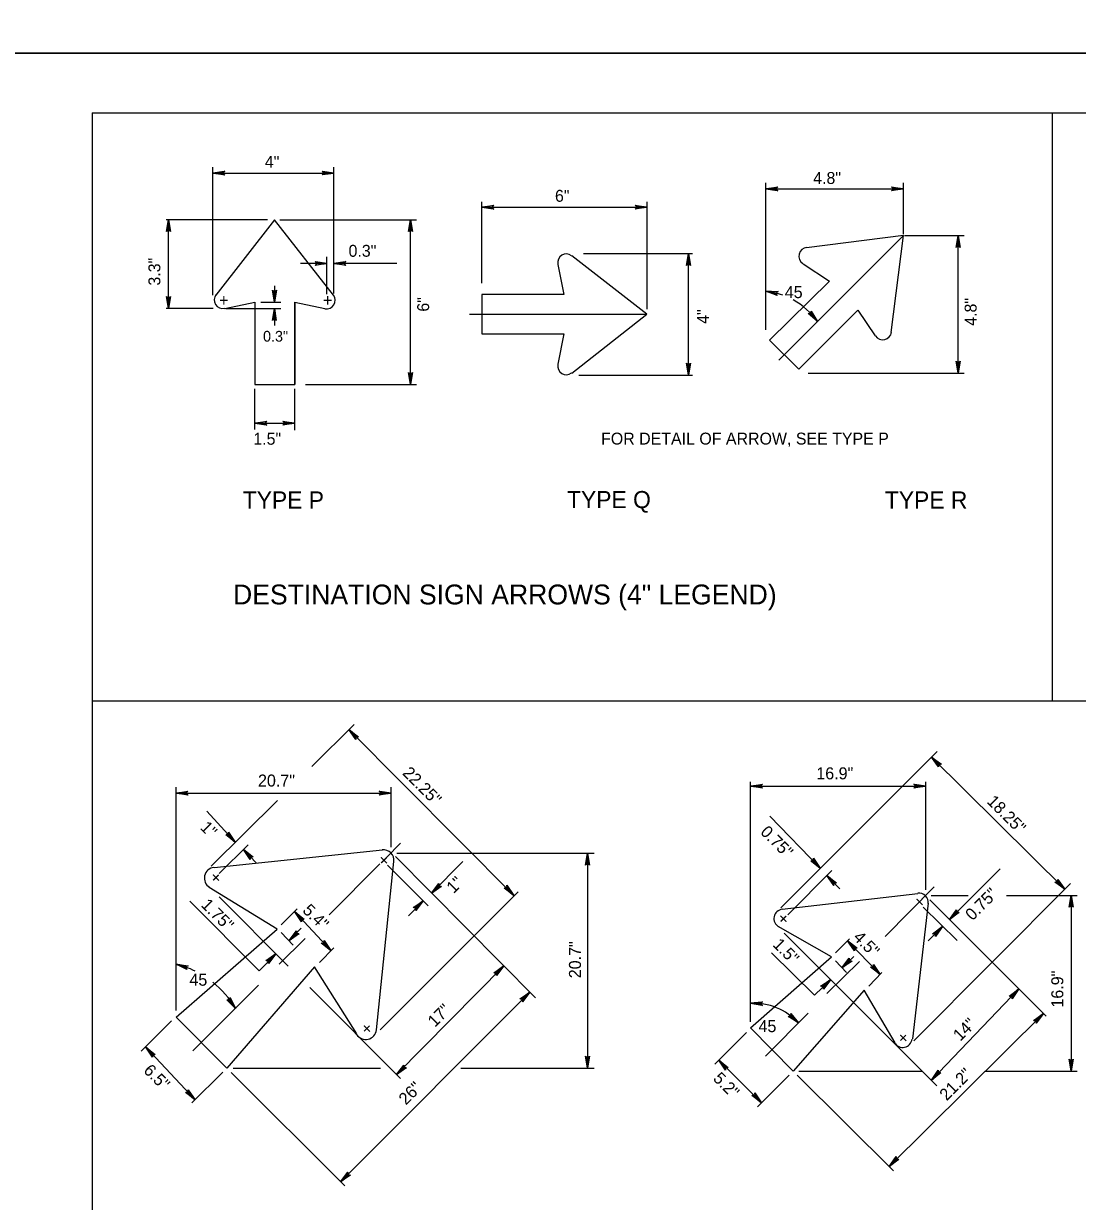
# Model space of a CAD drawing. Extents: x 638421 to 641849, y 297270 to 299646.
# Drawn here: x 640967.1 to 641232.4, y 298762.6 to 299059.1 of the extents above; entities that cross this region are included whole.
import ezdxf

# ---------------------------------------------------------------- set-up
doc = ezdxf.new("R2010")
doc.units = 0
for name, color, linetype in [('1', 7, 'Continuous'), ('2', 7, 'Continuous'), ('3', 7, 'Continuous'), ('XCS-GRID-HVGL', 7, 'Continuous')]:
    doc.layers.add(name, color=color, linetype=linetype)

# ---------------------------------------------------------------- blocks, each defined once
blk = doc.blocks.new('RARROW')
at = {"layer": '3'}
blk.add_lwpolyline([(-2.2695, 0.285), (-2.184875, 0.12075), (0, 0), (-2.2695, 0.285), (-2.38575, 0.384625), (0, 0), (-2.183125, -0.108), (-2.262875, -0.2705), (0, 0), (-2.38575, -0.379125), (-2.262875, -0.2705)], dxfattribs=at)

msp = doc.modelspace()

# ---------------------------------------------------------------- linework, layer by layer
at = {"layer": '1'}
for q in [(641770.31, 299036.63), (640984.31, 298472.63)]:
    msp.add_line((640984.31, 299036.63), q, dxfattribs=at)
for points in [[(641226.06, 298888.5), (641226.06, 299036.63)], [(641770.31, 298888.5), (640984.31, 298888.5)]]:
    msp.add_lwpolyline(points, dxfattribs=at)
at = {"layer": '2'}
for p, q in [((641014.69, 298990.75), (641014.69, 299023)), ((641014.69, 299021.5), (641045.19, 299021.5)), ((641045.19, 298991.13), (641045.19, 299023)), ((641153.94, 298982), (641153.94, 299019)), ((641188.56, 299006.13), (641188.56, 299019)), ((641153.94, 299017.5), (641188.56, 299017.5)), ((641082.44, 298993.75), (641082.44, 299014.25)), ((641082.44, 299012.88), (641124.06, 299012.88)), ((641124.06, 298987.25), (641124.06, 299014.25)), ((641028.44, 299009.75), (641002.94, 299009.75)), ((641003.56, 298987.38), (641003.56, 299009.75)), ((641030.19, 299009.75), (641015.44, 298990.75)), ((641045.06, 298990.75), (641030.19, 299009.75)), ((641031.56, 299009.75), (641065.94, 299009.75)), ((641064.44, 298968.25), (641064.44, 299009.75)), ((641157.19, 298974.38), (641188.56, 299005.75)), ((641188.56, 299005.75), (641164.19, 299002.63)), ((641185.44, 298981.38), (641188.56, 299005.75)), ((641188.81, 299005.75), (641203.81, 299005.75)), ((641202.31, 298971.13), (641202.31, 299005.75)), ((641043.44, 298991), (641043.44, 299000.38)), ((641045.19, 298991.13), (641045.19, 299000.38)), ((641123.94, 298986), (641105.06, 299000.63)), ((641108.06, 299001.25), (641135.44, 299001.25)), ((641134.46, 298970.63), (641134.46, 299001.25)), ((641043.44, 298998.75), (641036.81, 298998.75)), ((641061.01, 298998.75), (641045.19, 298998.75)), ((641101.56, 298998.5), (641103.06, 298990.88)), ((641163.31, 298998.63), (641169.94, 298994.25)), ((641169.94, 298994.25), (641154.81, 298979.38)), ((641030.19, 298993.13), (641030.19, 298989)), ((641017.69, 298987.38), (641025.31, 298989)), ((641025.31, 298989), (641025.31, 298968.25)), ((641025.31, 298989), (641025.31, 298968.25)), ((641026.81, 298989), (641031.81, 298989)), ((641035.31, 298968.25), (641035.31, 298989)), ((641035.31, 298989), (641042.94, 298987.38)), ((641035.31, 298989), (641035.31, 298968.25)), ((641035.31, 298989), (641035.31, 298968.25)), ((641082.44, 298990.88), (641082.44, 298981)), ((641103.06, 298990.88), (641082.44, 298990.88)), ((641014.81, 298987.38), (641002.94, 298987.38)), ((641017.94, 298987.38), (641031.81, 298987.38)), ((641030.19, 298987.38), (641030.19, 298983.13)), ((641079.31, 298986), (641123.94, 298986)), ((641105.06, 298971.13), (641123.94, 298986)), ((641162.19, 298972.13), (641177.06, 298987)), ((641177.06, 298987), (641181.44, 298980.5)), ((641082.44, 298981), (641103.06, 298981)), ((641103.06, 298981), (641101.56, 298973.38)), ((641154.81, 298979.38), (641162.19, 298972.13)), ((641106.81, 298970.63), (641135.44, 298970.63)), ((641164.56, 298971.13), (641203.81, 298971.13)), ((641025.31, 298968.25), (641035.31, 298968.25)), ((641038.06, 298968.25), (641065.94, 298968.25)), ((641025.31, 298956.88), (641025.31, 298967.13)), ((641035.31, 298956.75), (641035.31, 298967.13)), ((641025.31, 298958.5), (641035.31, 298958.5)), ((641039.62, 298872.11), (641050.28, 298882.68)), ((641048.98, 298881.39), (641090.44, 298839.63)), ((641157.69, 298836.5), (641197.03, 298875.84)), ((641195.61, 298874.43), (641229.19, 298841.17)), ((641005.44, 298810.63), (641005.44, 298866.88)), ((641059.56, 298851.75), (641059.56, 298866.88)), ((641150.06, 298807.75), (641150.06, 298868.25)), ((641150.06, 298867.13), (641150.06, 298867.13)), ((641150.06, 298867.13), (641194.19, 298867.13)), ((641194.19, 298841), (641194.19, 298868.25)), ((641005.44, 298865.38), (641059.56, 298865.38)), ((641014.31, 298847), (641030.98, 298863.54)), ((641020.36, 298853), (641013.18, 298860.81)), ((641167.63, 298846.44), (641154.9, 298859.59)), ((641016.31, 298845.13), (641023.56, 298852.38)), ((641061.94, 298852.75), (641058.41, 298849.2)), ((641015.06, 298846.63), (641057.44, 298851.13)), ((641022.4, 298851.21), (641025.69, 298847.75)), ((641059.56, 298850.25), (641059.56, 298850.25)), ((641059.56, 298850.25), (641059.56, 298850.25)), ((641059.56, 298850.25), (641059.56, 298850.25)), ((641060.69, 298849.38), (641095.95, 298813.81)), ((641061.06, 298850.25), (641110.69, 298850.25)), ((641109.06, 298850.25), (641109.06, 298796.13)), ((641056.75, 298847.53), (641043.98, 298834.69)), ((641060.19, 298848.13), (641055.81, 298805.75)), ((641058.69, 298847.25), (641068.94, 298837)), ((641069.77, 298840.21), (641077.68, 298848.12)), ((641159.44, 298834.75), (641170.56, 298845.88)), ((641200.15, 298833.52), (641212.91, 298846.28)), ((641015.31, 298843.88), (641015.31, 298843.88)), ((641169.31, 298844.63), (641172.54, 298841.27)), ((641030.94, 298831.13), (641013.81, 298841.63)), ((641056.81, 298805.75), (641091.56, 298840.5)), ((641158.06, 298836.13), (641192.19, 298840.13)), ((641183.98, 298829.29), (641196.31, 298841.75)), ((641191.19, 298803), (641230.6, 298842.59)), ((641008.9, 298838.18), (641026.36, 298820.67)), ((641016.31, 298839.25), (641033.68, 298821.84)), ((641067.69, 298838.25), (641063.94, 298834.5)), ((641194.81, 298837.63), (641190.81, 298803.5)), ((641194.19, 298839.63), (641194.19, 298839.63)), ((641194.19, 298839.63), (641194.19, 298839.63)), ((641195.19, 298838.5), (641203.69, 298830)), ((641195.19, 298838.5), (641224.46, 298809.23)), ((641195.56, 298839.63), (641204.84, 298839.63)), ((641214.47, 298839.63), (641232.31, 298839.63)), ((641230.81, 298839.63), (641230.81, 298839.63)), ((641230.81, 298839.63), (641230.81, 298795.38)), ((641031.94, 298832.25), (641035.92, 298836.23)), ((641035.31, 298835.5), (641044.43, 298825.71)), ((641193.56, 298836.63), (641202.06, 298828.25)), ((641005.44, 298809), (641030.94, 298831.13)), ((641030.94, 298831.13), (641030.94, 298831.13)), ((641033.94, 298828.25), (641036.94, 298831.38)), ((641170.44, 298824.13), (641157.06, 298831.75)), ((641198.37, 298831.77), (641194.78, 298828.19)), ((641031.43, 298822.33), (641037.94, 298828.75)), ((641031.94, 298830.25), (641034.94, 298827.13)), ((641158.56, 298830.13), (641197, 298791.69)), ((641171.44, 298825.13), (641174.98, 298828.66)), ((641174.52, 298828.21), (641182.69, 298819.69)), ((641030.56, 298824.88), (641026.36, 298820.67)), ((641041.56, 298822.75), (641045.14, 298826.43)), ((641155.37, 298825.18), (641166.18, 298814.53)), ((641150.06, 298806.25), (641170.44, 298824.13)), ((641169.31, 298814.88), (641177.5, 298822.96)), ((641171.44, 298823.13), (641174.19, 298820.25)), ((641173.09, 298821.4), (641176.06, 298824.25)), ((641005.44, 298821.88), (641005.44, 298821.88)), ((641040.31, 298821.63), (641018.19, 298796.13)), ((641040.31, 298821.63), (641040.31, 298821.63)), ((641050.94, 298804.75), (641040.31, 298821.63)), ((641087.97, 298821.85), (641060.94, 298794.5)), ((641174.69, 298820), (641174.69, 298820)), ((641179.81, 298816.75), (641183.16, 298820.17)), ((641009.69, 298800.5), (641026.18, 298817)), ((641015.19, 298817.38), (641015.19, 298817.38)), ((641039.1, 298816.4), (641061.94, 298793.5)), ((641170.25, 298818.44), (641166.18, 298814.53)), ((641171.69, 298817.13), (641171.69, 298817.13)), ((641195.59, 298793.1), (641217.62, 298816.07)), ((641217.56, 298816), (641217.56, 298816)), ((641046.81, 298767.5), (641094.54, 298815.23)), ((641178.69, 298815.75), (641160.81, 298795.38)), ((641186.44, 298802.5), (641178.69, 298815.75)), ((641004.31, 298808), (640996.69, 298800.38)), ((641018.19, 298796.13), (641005.44, 298809)), ((641153.81, 298799.13), (641164.56, 298810)), ((641184.94, 298771.38), (641223.78, 298809.91)), ((641149.06, 298805.13), (641141.06, 298797.13)), ((641160.81, 298795.38), (641150.06, 298806.25)), ((640997.81, 298801.38), (641010.22, 298788.16)), ((641155.56, 298800.88), (641155.56, 298800.88)), ((641188.31, 298800.38), (641188.31, 298800.38)), ((641019.81, 298796.13), (641056.95, 298796.13)), ((641077.16, 298796.13), (641110.69, 298796.13)), ((641142.06, 298798.13), (641152.81, 298787.38)), ((641162.19, 298795.38), (641193.31, 298795.38)), ((641209.08, 298795.38), (641232.31, 298795.38)), ((641017.19, 298795.13), (641009.44, 298787.38)), ((641019.31, 298795), (641047.94, 298766.5)), ((641159.81, 298794.38), (641151.81, 298786.38)), ((641161.81, 298794.38), (641186.06, 298770.25))]:
    msp.add_line(p, q, dxfattribs=at)
for centre, radius, start, end in [((641103.67, 298998.98), 2.16, 51.9885, 191.4212), ((641164.46, 299000.56), 2.21, 96.9885, 236.4212), ((641151.82, 298973.2), 18.65, 70.1319, 83.4312), ((641017.23, 298989.56), 2.16, 141.9885, 281.4212), ((641043.36, 298989.42), 2.16, 258.5788, 38.0115), ((641151.82, 298973.2), 18.65, 35.9325, 61.1367), ((641183.34, 298981.69), 2.21, 213.5788, 353.0115), ((641103.67, 298972.87), 2.16, 168.5788, 308.0115), ((641057.62, 298848.39), 2.7, 354.0498, 95.9502), ((641015.27, 298843.98), 2.7, 95.9502, 238.4461), ((641192.45, 298837.83), 2.36, 353.2204, 96.7795), ((641158.32, 298833.78), 2.36, 96.7795, 240.0676), ((640999.93, 298799.29), 23.64, 64.1532, 76.5153), ((640999.93, 298799.29), 23.64, 30.0986, 51.4068), ((641150.92, 298797.35), 15.12, 42.2634, 93.2507), ((641150.92, 298797.35), 15.12, 42.2634, 43.751), ((641053.21, 298806.04), 2.7, 211.5539, 354.0498), ((641188.39, 298803.71), 2.36, 209.9324, 353.2204)]:
    msp.add_arc(centre, radius, start, end, dxfattribs=at)
at = {"layer": 'XCS-GRID-HVGL'}
for points in [[(640944.31, 299645.63), (641785.31, 299645.63), (641785.31, 299051.63), (640944.31, 299051.63)], [(640944.31, 299051.63), (641785.31, 299051.63), (641785.31, 298457.63), (640944.31, 298457.63)]]:
    msp.add_lwpolyline(points, close=True, dxfattribs=at)

# ---------------------------------------------------------------- block references
at = {"layer": '2'}
for p, xscale, yscale, rotation in [((641014.69, 299021.5), 1.2574347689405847, 1.3092961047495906, 180), ((641153.94, 299017.5), 1.2574347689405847, 1.3092961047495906, 180), ((641082.44, 299012.88), 1.2574347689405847, 1.3092961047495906, 180), ((641003.56, 299009.75), 1.2574347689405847, 1.3092961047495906, 89.99999999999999), ((641064.44, 299009.75), 1.2574347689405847, 1.3092961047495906, 89.99999999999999), ((641202.31, 299005.75), 1.2574347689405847, 1.3092961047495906, 89.99999999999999), ((641134.46, 299001.25), 1.2574347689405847, 1.3092961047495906, 89.99999999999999), ((641045.19, 298998.75), 1.2574347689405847, 1.3092961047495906, 180), ((641030.19, 298989), 1.2574347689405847, 1.3092961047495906, -90.00000000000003), ((641153.95, 298991.73), 1.2574347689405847, 1.3092961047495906, 169.44923148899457), ((641003.56, 298987.38), 1.2574347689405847, 1.3092961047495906, -90.00000000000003), ((641030.19, 298987.38), 1.2574347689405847, 1.3092961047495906, 89.99999999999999), ((641166.92, 298984.14), 1.257434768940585, 1.3092961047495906, -49.33525857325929), ((641134.46, 298970.63), 1.2574347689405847, 1.3092961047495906, -90.00000000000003), ((641202.31, 298971.13), 1.2574347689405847, 1.3092961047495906, -90.00000000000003), ((641064.44, 298968.25), 1.2574347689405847, 1.3092961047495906, -90.00000000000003), ((641025.31, 298958.5), 1.2574347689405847, 1.3092961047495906, 180), ((641048.98, 298881.39), 1.257434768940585, 1.3092961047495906, 133.27939444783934), ((641195.61, 298874.43), 1.2574347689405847, 1.3092961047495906, 135.61891032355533), ((641150.06, 298867.13), 1.2574347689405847, 1.3092961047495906, 180), ((641005.44, 298865.38), 1.2574347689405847, 1.3092961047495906, 180), ((641020.36, 298853), 1.257434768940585, 1.3092961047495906, -46.72060555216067), ((641022.4, 298851.21), 1.257434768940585, 1.3092961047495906, 133.27939444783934), ((641109.06, 298850.25), 1.2574347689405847, 1.3092961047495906, 89.99999999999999), ((641167.63, 298846.44), 1.257434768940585, 1.3092961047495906, -46.72060555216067), ((641169.31, 298844.63), 1.257434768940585, 1.3092961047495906, 133.27939444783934), ((641229.19, 298841.17), 1.257434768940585, 1.3092961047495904, -44.89188331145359), ((641069.77, 298840.21), 1.2574347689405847, 1.3092961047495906, -136.72060555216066), ((641090.44, 298839.63), 1.257434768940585, 1.3092961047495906, -46.72060555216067), ((641067.69, 298838.25), 1.257434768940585, 1.3092961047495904, 43.27939444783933), ((641230.81, 298839.63), 1.2574347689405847, 1.3092961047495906, 89.99999999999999), ((641035.31, 298835.5), 1.257434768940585, 1.3092961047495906, 133.27939444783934), ((641200.15, 298833.52), 1.257434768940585, 1.3092961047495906, -134.67395762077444), ((641198.37, 298831.77), 1.257434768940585, 1.309296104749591, 45.50955017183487), ((641033.94, 298828.25), 1.2574347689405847, 1.3092961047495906, -136.72060555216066), ((641044.43, 298825.71), 1.257434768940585, 1.3092961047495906, -46.72060555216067), ((641174.52, 298828.21), 1.257434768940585, 1.3092961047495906, 133.27939444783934), ((641030.56, 298824.88), 1.257434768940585, 1.3092961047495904, 43.27939444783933), ((641005.44, 298822.28), 1.2574347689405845, 1.3092961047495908, 163.80944818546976), ((641087.97, 298821.85), 1.257434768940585, 1.3092961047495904, 43.27939444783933), ((641173.09, 298821.4), 1.2574347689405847, 1.3092961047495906, -136.72060555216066), ((641182.69, 298819.69), 1.257434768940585, 1.3092961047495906, -46.72060555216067), ((641170.25, 298818.44), 1.257434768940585, 1.3092961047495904, 43.27939444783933), ((641217.62, 298816.07), 1.2574347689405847, 1.3092961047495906, 47.006569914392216), ((641020.37, 298811.15), 1.257434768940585, 1.3092961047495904, -55.73238514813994), ((641094.54, 298815.23), 1.257434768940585, 1.3092961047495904, 43.27939444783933), ((641150.06, 298812.45), 1.2574347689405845, 1.3092961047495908, 178.3226404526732), ((641223.78, 298809.91), 1.2574347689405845, 1.3092961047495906, 44.994727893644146), ((641162.11, 298807.52), 1.2574347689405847, 1.3092961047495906, -42.27401175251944), ((640997.81, 298801.38), 1.257434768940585, 1.3092961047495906, 133.27939444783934), ((641109.06, 298796.13), 1.2574347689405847, 1.3092961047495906, -90.00000000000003), ((641142.06, 298798.13), 1.257434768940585, 1.3092961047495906, 133.27939444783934), ((641230.81, 298795.38), 1.2574347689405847, 1.3092961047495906, -90.00000000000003), ((641060.94, 298794.5), 1.2574347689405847, 1.3092961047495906, -136.72060555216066), ((641195.59, 298793.1), 1.2574347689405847, 1.3092961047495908, -132.89815458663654), ((641010.22, 298788.16), 1.257434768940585, 1.3092961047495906, -46.72060555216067), ((641152.81, 298787.38), 1.257434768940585, 1.3092961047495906, -46.72060555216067), ((641184.94, 298771.38), 1.257434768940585, 1.3092961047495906, -134.7356981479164), ((641046.81, 298767.5), 1.2574347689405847, 1.3092961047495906, -136.72060555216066)]:
    msp.add_blockref('RARROW', p, dxfattribs=dict(at, xscale=xscale, yscale=yscale, rotation=rotation))
at = {"layer": '2', "xscale": 1.2574347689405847, "yscale": 1.3092961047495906}
for p in [(641045.19, 299021.5), (641188.56, 299017.5), (641124.06, 299012.88), (641043.44, 298998.75), (641035.31, 298958.5), (641194.19, 298867.13), (641059.56, 298865.38)]:
    msp.add_blockref('RARROW', p, dxfattribs=at)

# ---------------------------------------------------------------- texts
at = {"layer": '2'}
for s, height, p in [('4"', 3, (641027.8, 299022.82)), ('4.8"', 3, (641165.84, 299018.75)), ('6"', 3, (641100.84, 299014.25)), ('0.3"', 3, (641048.87, 299000.41)), ('45', 3.022, (641158.69, 298990)), ('+', 3.02, (641016.31, 298988)), ('+', 3.02, (641042.44, 298988)), ('0.3"', 2.699, (641027.35, 298979.05)), ('1.5"', 3, (641024.9, 298953.09)), ('FOR DETAIL OF ARROW, SEE TYPE P', 3, (641112.44, 298953.13)), ('TYPE P', 4.3, (641022.24, 298937.03)), ('TYPE Q', 4.3, (641103.88, 298937.13)), ('TYPE R', 4.3, (641183.89, 298937.03)), ('DESTINATION SIGN ARROWS (4" LEGEND)', 5, (641019.79, 298912.88)), ('20.7"', 3.022, (641026.08, 298867.03)), ('16.9"', 3.022, (641166.63, 298868.84)), ('45', 3.022, (641008.81, 298816.88)), ('45', 3.022, (641152.08, 298805.19))]:
    msp.add_text(s, height=height, dxfattribs=at).set_placement(p)
for s, height, rotation, p in [('3.3"', 3, 90, (641001.49, 298993.15)), ('6"', 3, 90, (641069.16, 298986.59)), ('4.8"', 3, 90, (641206.97, 298983.03)), ('4"', 3, 90, (641139.58, 298983.53)), ('22.25"', 3.022, 315, (641062.27, 298870.24)), ('18.25"', 3.022, 315, (641209.38, 298863.07)), ('1"', 3.022, 315, (641011.31, 298856.51)), ('0.75"', 3.022, 315, (641152.36, 298855.36)), ('+', 3.02, 45, (641057.96, 298846.6)), ('+', 3.02, 45, (641015.69, 298842.25)), ('1"', 3.022, 45, (641075.33, 298839.95)), ('0.75"', 3.022, 45, (641205.95, 298833.1)), ('1.75"', 3.022, 315, (641011.57, 298837.01)), ('5.4"', 3.022, 315, (641037.09, 298835.64)), ('+', 3.02, 45, (641192.81, 298836.13)), ('+', 3.02, 45, (641158.56, 298831.88)), ('20.7"', 3.022, 90, (641107.38, 298818.76)), ('1.5"', 3.022, 315, (641155.48, 298827.03)), ('4.5"', 3.022, 315, (641175.72, 298828.84)), ('16.9"', 3.022, 90, (641228.81, 298811.37)), ('17"', 3.022, 45, (641070.62, 298806.27)), ('14"', 3.022, 45, (641202.85, 298802.74)), ('+', 3.02, 45, (641053.69, 298804.25)), ('+', 3.02, 45, (641188.69, 298801.88)), ('6.5"', 3.022, 315, (640997.06, 298795.32)), ('5.2"', 3.022, 315, (641140.45, 298793.31)), ('21.2"', 3.022, 45, (641199.44, 298787.74)), ('26"', 3.022, 45, (641063.31, 298786.67))]:
    msp.add_text(s, height=height, rotation=rotation, dxfattribs=at).set_placement(p)

doc.saveas('drawing.dxf')
